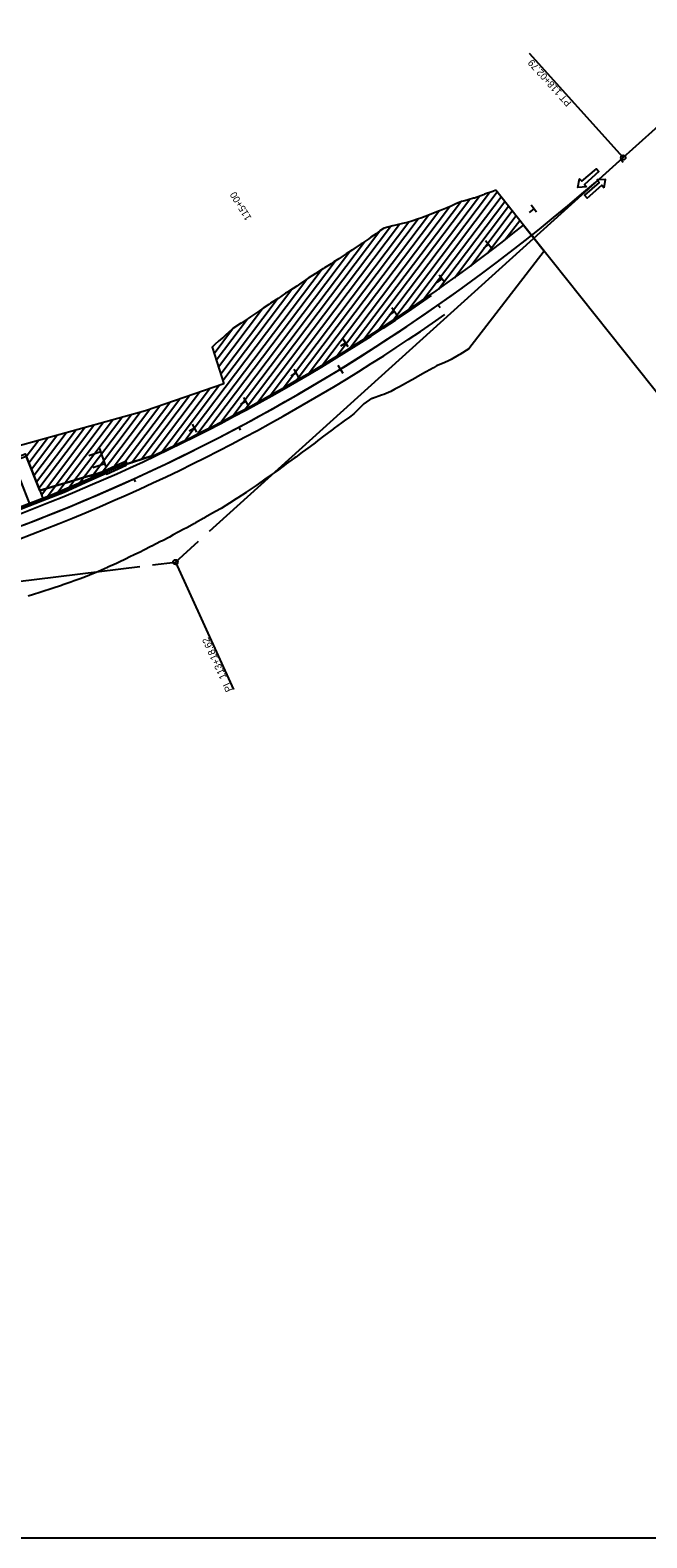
# Model space of a CAD drawing. Extents: x 1568809 to 1572786, y 728326 to 734907.
# Drawn here: x 1571471 to 1571999, y 731509 to 732799 of the extents above; entities that cross this region are included whole.
import ezdxf

# ---------------------------------------------------------------- set-up
doc = ezdxf.new("R2010")
doc.units = 0
for name, color, linetype in [('R_Horz Alg', 7, 'Continuous'), ('R_Horz Alg Annot', 7, 'Continuous'), ('R_MOT', 7, 'Continuous'), ('R_No Plot', 7, 'Continuous'), ('R_Striping', 7, 'Continuous')]:
    doc.layers.add(name, color=color, linetype=linetype)

msp = doc.modelspace()

# ---------------------------------------------------------------- linework, layer by layer
at = {"layer": 'R_Horz Alg'}
msp.add_line((1571978.5, 732690.3), (1572468.4, 733132.6), dxfattribs=at)
msp.add_arc((1570881.5, 733905.4), 1637, 277.05, 312.0749, dxfattribs=at)
at = {"layer": 'R_Horz Alg Annot'}
for p, q in [((1571624.2, 732370.5), (1571978.5, 732690.3)), ((1571595, 732344.1), (1571614.8, 732362)), ((1571575.4, 732341.7), (1571595, 732344.1)), ((1571082.4, 732280.7), (1571564.6, 732340.4))]:
    msp.add_line(p, q, dxfattribs=at)
for points in [[(1571978.5, 732690.3), (1571898.1, 732779.3)], [(1571978.4, 732686.2), (1571976.4, 732688.4)], [(1571901.9, 732621.5), (1571900.1, 732623.8)], [(1571821.6, 732561.6), (1571819.9, 732564)], [(1571734.2, 732512.7), (1571738.4, 732505.8)], [(1571650.9, 732457), (1571649.5, 732459.7)], [(1571561, 732412.8), (1571559.8, 732415.5)], [(1571595, 732344.1), (1571644.9, 732235)]]:
    msp.add_lwpolyline(points, dxfattribs=at)
for centre in [(1571978.5, 732690.3), (1571595, 732344.1)]:
    msp.add_circle(centre, 2, dxfattribs=at)
at = {"layer": 'R_MOT'}
for p, q in [((1571744.4, 732527.2), (1571839.1, 732652.3)), ((1571756.5, 732534.8), (1571847.1, 732654.6)), ((1571768.7, 732542.7), (1571855.4, 732657.3)), ((1571781.2, 732550.9), (1571863.9, 732660.3)), ((1571793.9, 732559.5), (1571870.6, 732660.9)), ((1571806.9, 732568.4), (1571873.8, 732656.8)), ((1571820.2, 732577.7), (1571877, 732652.8)), ((1571709.6, 732506), (1571811.8, 732641.1)), ((1571721, 732512.8), (1571820.6, 732644.5)), ((1571732.6, 732519.9), (1571829.7, 732648.3)), ((1571833.9, 732587.5), (1571880.2, 732648.7)), ((1571847.9, 732597.7), (1571883.5, 732644.7)), ((1571862.3, 732608.5), (1571886.7, 732640.7)), ((1571901.8, 732646.5), (1571897.8, 732643.2)), ((1571904.3, 732643.7), (1571899.5, 732649.6)), ((1571654.8, 732475), (1571770.1, 732627.5)), ((1571665.4, 732480.8), (1571779.3, 732631.3)), ((1571676.2, 732486.8), (1571787, 732633.2)), ((1571687.2, 732493), (1571794.8, 732635.2)), ((1571698.3, 732499.4), (1571803, 732637.8)), ((1571877.2, 732619.9), (1571889.9, 732636.6)), ((1571892.7, 732632), (1571893.1, 732632.6)), ((1571644.2, 732469.3), (1571756.9, 732618.2)), ((1571862.9, 732616), (1571858.8, 732612.8)), ((1571865.3, 732613), (1571860.6, 732619.1)), ((1571623.5, 732458.5), (1571731.7, 732601.6)), ((1571633.8, 732463.9), (1571744.1, 732609.7)), ((1571613.3, 732453.3), (1571719.8, 732594.1)), ((1571825.4, 732583.6), (1571820.9, 732589.8)), ((1571603.2, 732448.3), (1571707.6, 732586.2)), ((1571635.7, 732499.5), (1571694.8, 732577.6)), ((1571823.1, 732586.6), (1571818.8, 732583.5)), ((1571633.8, 732505.3), (1571682.1, 732569.1)), ((1571784.6, 732555.4), (1571780.3, 732561.7)), ((1571630, 732516.9), (1571656.9, 732552.4)), ((1571631.9, 732511.1), (1571669.7, 732561.1)), ((1571782.4, 732558.5), (1571778, 732555.5)), ((1571628.2, 732522.7), (1571644, 732543.7)), ((1571740.8, 732531.6), (1571736.4, 732528.8)), ((1571742.9, 732528.4), (1571738.8, 732534.9)), ((1571698.4, 732506), (1571694, 732503.3)), ((1571700.5, 732502.8), (1571696.6, 732509.3)), ((1571565.7, 732431.8), (1571607.2, 732486.7)), ((1571574, 732434.5), (1571615.7, 732489.6)), ((1571583.4, 732438.6), (1571624.2, 732492.5)), ((1571593.3, 732443.4), (1571632.6, 732495.5)), ((1571657.3, 732478.4), (1571653.6, 732485.1)), ((1571522.3, 732416), (1571565, 732472.4)), ((1571531.6, 732420), (1571573.2, 732474.9)), ((1571540.9, 732423.9), (1571581.7, 732477.9)), ((1571549.1, 732426.6), (1571590.2, 732480.8)), ((1571557.4, 732429.2), (1571598.7, 732483.7)), ((1571655.3, 732481.7), (1571650.8, 732479.1)), ((1571478.1, 732407.3), (1571517.3, 732459.1)), ((1571480.3, 732401.8), (1571525.3, 732461.3)), ((1571485.2, 732400), (1571533.2, 732463.5)), ((1571494.5, 732404), (1571541.2, 732465.7)), ((1571503.8, 732408), (1571549.1, 732467.9)), ((1571513, 732412), (1571557.1, 732470.1)), ((1571611.5, 732458.7), (1571606.9, 732456.3)), ((1571613.3, 732455.4), (1571609.8, 732462.2)), ((1571467.4, 732434.5), (1571477.6, 732448)), ((1571469.5, 732429.1), (1571485.5, 732450.2)), ((1571471.7, 732423.6), (1571493.5, 732452.4)), ((1571473.8, 732418.2), (1571501.4, 732454.6)), ((1571476, 732412.7), (1571509.4, 732456.8)), ((1571520.8, 732435.4), (1571531.1, 732438.9)), ((1571535.4, 732426.1), (1571530.3, 732441.3)), ((1571535.3, 732420.8), (1571517.1, 732412.6)), ((1571524.3, 732425.1), (1571534.6, 732428.6)), ((1571535.6, 732422.6), (1571536.8, 732419.9)), ((1571537.4, 732423.4), (1571538.6, 732420.7)), ((1571539.2, 732424.3), (1571540.5, 732421.5)), ((1571541, 732425.1), (1571542.3, 732422.4)), ((1571542.9, 732425.9), (1571544.1, 732423.2)), ((1571544.7, 732426.7), (1571545.9, 732424)), ((1571546.5, 732427.6), (1571547.7, 732424.8)), ((1571548.3, 732428.4), (1571549.6, 732425.7)), ((1571550.1, 732429.2), (1571551.4, 732426.5)), ((1571552, 732430), (1571553.2, 732427.4)), ((1571517.1, 732412.6), (1571498.9, 732404.4))]:
    msp.add_line(p, q, dxfattribs=at)
for points in [[(1571947, 732665.3), (1571939.7, 732664.8), (1571941.1, 732672.1), (1571943, 732670), (1571955.5, 732680.8), (1571957.7, 732678.3), (1571945.2, 732667.4)], [(1571962, 732664.5), (1571963.4, 732671.7), (1571956, 732671.2), (1571957.9, 732669.1), (1571945.4, 732658.3), (1571947.6, 732655.7), (1571960.1, 732666.6)], [(1571517, 732413.6), (1571534.9, 732421.7), (1571535.8, 732419.9), (1571517.8, 732411.8)], [(1571498.9, 732405.5), (1571517, 732413.6), (1571517.8, 732411.8), (1571499.8, 732403.7)], [(1571462.2, 732391.3), (1571480.6, 732398.4), (1571481.3, 732396.5), (1571462.9, 732389.4)], [(1571480.6, 732398.4), (1571499, 732405.5), (1571499.7, 732403.6), (1571481.3, 732396.5)]]:
    msp.add_lwpolyline(points, close=True, dxfattribs=at)
msp.add_lwpolyline([(1571551.6, 732429.9), (1571534.7, 732422.2), (1571536, 732419.5), (1571552.8, 732427.1)], dxfattribs=at)
for centre, radius, start, end in [((1571552.2, 732428.5), 1.5, 294.4946, 114.4946), ((1570881.5, 733905.4), 1623, 277.05, 292.3585)]:
    msp.add_arc(centre, radius, start, end, dxfattribs=at)
at = {"layer": 'R_No Plot'}
for p, q in [((1571893.2, 732632.4), (1571869.5, 732662.3)), ((1571893.2, 732632.4), (1571869.5, 732662.3)), ((1571893.2, 732632.4), (1571869.5, 732662.3)), ((1572786.1, 731508.9), (1571893.2, 732632.4)), ((1572786.1, 731508.9), (1571893.2, 732632.4)), ((1571893.2, 732632.4), (1571905.7, 732616.7)), ((1571905.7, 732616.7), (1571910.8, 732610.2)), ((1571910.8, 732610.2), (1571846.2, 732526.5)), ((1571535.3, 732420.8), (1571517.1, 732412.6)), ((1571517.1, 732412.6), (1571498.9, 732404.4)), ((1569148.8, 731508.9), (1572786.1, 731508.9)), ((1569203.7, 731508.9), (1572786.1, 731508.9))]:
    msp.add_line(p, q, dxfattribs=at)
for points in [[(1571869.5, 732662.3), (1571866.7, 732661.2), (1571859.8, 732658.9), (1571858.7, 732658.5), (1571851, 732655.7), (1571850.2, 732655.5), (1571842.8, 732653.4), (1571840.1, 732652.8), (1571835.1, 732650.6), (1571831, 732648.8), (1571827.7, 732647.4), (1571821.9, 732645), (1571820.2, 732644.4), (1571812.7, 732641.4), (1571812.6, 732641.4), (1571805.1, 732638.6), (1571803.3, 732637.9), (1571797.4, 732635.9), (1571793.7, 732634.9), (1571789.4, 732633.8), (1571783.7, 732632.4), (1571781.3, 732631.8), (1571773.7, 732630)], [(1571869.5, 732662.3), (1571866.7, 732661.2), (1571859.8, 732658.9), (1571858.7, 732658.5), (1571851, 732655.7), (1571850.2, 732655.5), (1571842.8, 732653.4), (1571840.1, 732652.8), (1571835.1, 732650.6), (1571831, 732648.8), (1571827.7, 732647.4), (1571821.9, 732645), (1571820.2, 732644.4), (1571812.7, 732641.4), (1571812.6, 732641.4), (1571805.1, 732638.6), (1571803.3, 732637.9), (1571797.4, 732635.9), (1571793.7, 732634.9), (1571789.4, 732633.8), (1571783.7, 732632.4), (1571781.3, 732631.8), (1571773.7, 732630)], [(1571869.5, 732662.3), (1571866.7, 732661.2), (1571859.8, 732658.9), (1571858.7, 732658.5), (1571851, 732655.7), (1571850.2, 732655.5), (1571842.8, 732653.4), (1571840.1, 732652.8), (1571835.1, 732650.6), (1571831, 732648.8), (1571827.7, 732647.4), (1571821.9, 732645), (1571820.2, 732644.4), (1571812.7, 732641.4), (1571812.6, 732641.4), (1571805.1, 732638.6), (1571803.3, 732637.9), (1571797.4, 732635.9), (1571793.7, 732634.9), (1571789.4, 732633.8), (1571783.7, 732632.4), (1571781.3, 732631.8), (1571773.7, 732630)], [(1571773.7, 732630), (1571773.3, 732629.7), (1571770.2, 732627.6), (1571766.9, 732625.2), (1571762.4, 732622.1), (1571760.6, 732620.8), (1571754.6, 732616.7), (1571754.2, 732616.4), (1571747.8, 732612.1), (1571746.7, 732611.4), (1571741.3, 732607.9), (1571738.8, 732606.2), (1571734.9, 732603.6), (1571730.8, 732601), (1571728.4, 732599.5), (1571722.8, 732596), (1571721.8, 732595.4), (1571715.3, 732591.2), (1571714.7, 732590.9), (1571708.8, 732587), (1571706.7, 732585.7), (1571702.3, 732582.9), (1571702.3, 732582.8), (1571698.9, 732580.3), (1571695.9, 732578.4), (1571690.9, 732575.2), (1571689.4, 732574.2), (1571683.1, 732569.7), (1571676.5, 732565.6), (1571675, 732564.7), (1571670.1, 732561.3), (1571667.1, 732559.3), (1571663.7, 732556.9), (1571659.2, 732553.9), (1571657.2, 732552.6), (1571651.3, 732548.7), (1571650.7, 732548.3), (1571644.3, 732543.9), (1571643.4, 732543.2), (1571638.3, 732538.7), (1571636.2, 732536.5), (1571632.3, 732533.5), (1571628.7, 732530.4), (1571626.4, 732528.1), (1571636.5, 732496.8)], [(1571773.7, 732630), (1571773.3, 732629.7), (1571770.2, 732627.6), (1571766.9, 732625.2), (1571762.4, 732622.1), (1571760.6, 732620.8), (1571754.6, 732616.7), (1571754.2, 732616.4), (1571747.8, 732612.1), (1571746.7, 732611.4), (1571741.3, 732607.9), (1571738.8, 732606.2), (1571734.9, 732603.6), (1571730.8, 732601), (1571728.4, 732599.5), (1571722.8, 732596), (1571721.8, 732595.4), (1571715.3, 732591.2), (1571714.7, 732590.9), (1571708.8, 732587), (1571706.7, 732585.7), (1571702.3, 732582.9), (1571702.3, 732582.8), (1571698.9, 732580.3), (1571695.9, 732578.4), (1571690.9, 732575.2), (1571689.4, 732574.2), (1571683.1, 732569.7), (1571676.5, 732565.6), (1571675, 732564.7), (1571670.1, 732561.3), (1571667.1, 732559.3), (1571663.7, 732556.9), (1571659.2, 732553.9), (1571657.2, 732552.6), (1571651.3, 732548.7), (1571650.7, 732548.3), (1571644.3, 732543.9), (1571643.4, 732543.2), (1571638.3, 732538.7), (1571636.2, 732536.5), (1571632.3, 732533.5), (1571628.7, 732530.4), (1571626.4, 732528.1), (1571636.5, 732496.8)], [(1571773.7, 732630), (1571773.3, 732629.7), (1571770.2, 732627.6), (1571766.9, 732625.2), (1571762.4, 732622.1), (1571760.6, 732620.8), (1571754.6, 732616.7), (1571754.2, 732616.4), (1571747.8, 732612.1), (1571746.7, 732611.4), (1571741.3, 732607.9), (1571738.8, 732606.2), (1571734.9, 732603.6), (1571730.8, 732601), (1571728.4, 732599.5), (1571722.8, 732596), (1571721.8, 732595.4), (1571715.3, 732591.2), (1571714.7, 732590.9), (1571708.8, 732587), (1571706.7, 732585.7), (1571702.3, 732582.9), (1571702.3, 732582.8), (1571698.9, 732580.3), (1571695.9, 732578.4), (1571690.9, 732575.2), (1571689.4, 732574.2), (1571683.1, 732569.7), (1571676.5, 732565.6), (1571675, 732564.7), (1571670.1, 732561.3), (1571667.1, 732559.3), (1571663.7, 732556.9), (1571659.2, 732553.9), (1571657.2, 732552.6), (1571651.3, 732548.7), (1571650.7, 732548.3), (1571644.3, 732543.9), (1571643.4, 732543.2), (1571638.3, 732538.7), (1571636.2, 732536.5), (1571632.3, 732533.5), (1571628.7, 732530.4), (1571626.4, 732528.1), (1571636.5, 732496.8)], [(1571846.2, 732526.5), (1571838.5, 732521.8), (1571837.4, 732521.1), (1571831.2, 732517.6), (1571828.4, 732516.1), (1571823.6, 732514), (1571818.7, 732512), (1571815.9, 732510.4), (1571809.8, 732507), (1571808.6, 732506.3), (1571801.3, 732502.2), (1571800.8, 732501.9), (1571794.1, 732498.1), (1571791.9, 732496.9), (1571786.8, 732494.1), (1571782.9, 732492), (1571779.4, 732490.1), (1571773.5, 732487.6), (1571771.6, 732486.9), (1571763.7, 732484), (1571763.3, 732484.5)], [(1571636.5, 732496.8), (1571569.3, 732473.6), (1571454.2, 732441.5)], [(1571636.5, 732496.8), (1571569.3, 732473.6), (1571454.2, 732441.5)], [(1571636.5, 732496.8), (1571569.3, 732473.6), (1571454.2, 732441.5)], [(1571763.3, 732484.5), (1571756.5, 732479.7), (1571755.2, 732478.4), (1571750.4, 732473.6), (1571747.7, 732471), (1571744, 732468.2), (1571739.4, 732465), (1571737.2, 732463.4), (1571731.1, 732458.8), (1571730.5, 732458.3), (1571723.8, 732453.3), (1571722.9, 732452.6), (1571717.1, 732448.2), (1571714.6, 732446.3), (1571710.3, 732443.1), (1571706.3, 732440.2), (1571703.6, 732438.1), (1571698.1, 732433.9), (1571696.8, 732433), (1571690, 732428.2), (1571689.6, 732427.9), (1571683.2, 732423.1), (1571681.3, 732421.7), (1571676.3, 732418.1), (1571672.8, 732415.8), (1571669.4, 732413.3), (1571664.3, 732409.7), (1571662.5, 732408.5), (1571655.7, 732403.9), (1571655.5, 732403.8), (1571648.4, 732399.2), (1571647, 732398.3), (1571641.3, 732394.6), (1571638.3, 732392.6), (1571634.1, 732390.1), (1571629.4, 732387.3), (1571626.8, 732385.9), (1571620.3, 732382.3), (1571619.4, 732381.8), (1571612.1, 732377.7), (1571611.3, 732377.2), (1571604.7, 732373.5), (1571602.2, 732372.2), (1571597.3, 732369.6), (1571593.1, 732367.3), (1571589.9, 732365.5), (1571583.9, 732362.4), (1571582.4, 732361.6), (1571574.9, 732357.7), (1571574.7, 732357.6), (1571567.4, 732353.9), (1571565.5, 732352.9), (1571559.8, 732350.2), (1571556.1, 732348.5), (1571552.2, 732346.5), (1571546.8, 732343.9), (1571544.6, 732342.9), (1571537.3, 732339.7), (1571536.9, 732339.5), (1571529.2, 732336.1), (1571527.8, 732335.5), (1571521.4, 732332.8), (1571518.2, 732331.5), (1571513.5, 732329.8), (1571508.5, 732328), (1571505.5, 732327), (1571498.7, 732324.6), (1571497.6, 732324.2), (1571489.6, 732321.6), (1571488.8, 732321.3), (1571481.5, 732319), (1571479, 732318.1), (1571473.5, 732316.4), (1571469.1, 732315)], [(1571080.6, 732295.6), (1571151.9, 732306.1), (1571232.9, 732321.9), (1571308.7, 732340.6), (1571366.5, 732357.6), (1571461.8, 732390.6), (1571470.4, 732394.1), (1571467.3, 732402), (1571456.1, 732430.4), (1571467.3, 732434.8), (1571478.9, 732405.4), (1571481.6, 732398.5), (1571540.5, 732423.8), (1571576, 732435.2)], [(1571080.6, 732295.6), (1571151.9, 732306.1), (1571232.9, 732321.9), (1571308.7, 732340.6), (1571366.5, 732357.6), (1571461.8, 732390.6), (1571470.4, 732394.1), (1571467.3, 732402), (1571456.1, 732430.4), (1571467.3, 732434.8), (1571478.9, 732405.4), (1571481.6, 732398.5), (1571540.5, 732423.8), (1571576, 732435.2)], [(1571080.6, 732295.6), (1571151.9, 732306.1), (1571232.9, 732321.9), (1571308.7, 732340.6), (1571366.5, 732357.6), (1571461.8, 732390.6), (1571470.4, 732394.1), (1571467.3, 732402), (1571456.1, 732430.4), (1571467.3, 732434.8), (1571478.9, 732405.4), (1571481.6, 732398.5), (1571540.5, 732423.8), (1571576, 732435.2)], [(1571469.4, 732396.8), (1571455.4, 732432.3), (1571466.5, 732436.7), (1571478.9, 732405.4), (1571492.3, 732409.3), (1571504.4, 732412.9), (1571516.4, 732416.4), (1571528.5, 732419.9), (1571540.5, 732423.8), (1571576, 732435.2)], [(1571576, 732435.2), (1571540.5, 732423.8), (1571528.5, 732419.9), (1571516.4, 732416.4), (1571504.4, 732412.9), (1571492.3, 732409.3), (1571478.9, 732405.4), (1571467.3, 732434.8)], [(1571576, 732435.2), (1571540.5, 732423.8), (1571528.5, 732419.9), (1571516.4, 732416.4), (1571504.4, 732412.9), (1571492.3, 732409.3), (1571478.9, 732405.4), (1571467.3, 732434.8)]]:
    msp.add_lwpolyline(points, dxfattribs=at)
for radius, start, end in [(1626, 295.2862, 308.4772), (1626, 295.2862, 308.4772), (1626, 295.2862, 308.4772), (1626, 295.2862, 308.4772), (1626, 295.2862, 308.4772), (1626, 295.2862, 308.4772), (1623, 277.05, 292.3585)]:
    msp.add_arc((1570881.5, 733905.4), radius, start, end, dxfattribs=at)
at = {"layer": 'R_Striping'}
for radius, end in [(1637, 305.877), (1627, 304.9772), (1647, 304.9772)]:
    msp.add_arc((1570881.5, 733905.4), radius, 277.05, end, dxfattribs=at)

# ---------------------------------------------------------------- texts
at = {"layer": 'R_Horz Alg Annot'}
for s, rotation, p in [('PT 118+02.79', 132.0749, (1571934.6, 732737.4)), ('115+00', 121.4772, (1571660.5, 732638.7)), ('PI  113+18.62', 114.5625, (1571644, 732234.6))]:
    msp.add_text(s, height=6, rotation=rotation, dxfattribs=at).set_placement(p)

doc.saveas('drawing.dxf')
